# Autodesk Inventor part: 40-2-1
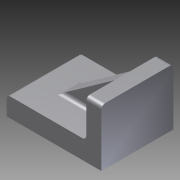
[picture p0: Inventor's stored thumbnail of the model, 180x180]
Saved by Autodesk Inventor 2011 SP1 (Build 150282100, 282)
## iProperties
Created: 2014-01
Part Number: 40-2-1
Document SubType Name: Modeling
Designer: Administrator
Density: 1 g/cm^3
Author: Administrator
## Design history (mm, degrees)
sketch "草图1"
  geometry: L1 (-12.5, 9.5)-(12.5, 9.5); L2 (12.5, 9.5)-(12.5, -9.5); L3 (12.5, -9.5)-(-12.5, -9.5); L4 (-12.5, -9.5)-(-12.5, 9.5); 3 further points
  constraints: 8 end point, 2 midpoint, 2 parallel, 1 horizontal, 1 horizontal alignment, 1 perpendicular, 1 vertical alignment
  dimensions: "d0" = 25 distance of L1.start L1.end; "d1" = 19 distance of L1.end L2.end
extrude "拉伸1" new body sketch "草图1" distance "d2" = 5; taper "d3" = 0 deg
sketch "草图2"
  geometry: L1 (12.5, -9.5)-(-12.5, -9.5) reference; L2 (12.5, 9.5)-(8.5, 9.5); L3 (8.5, 9.5)-(8.5, -9.5); L4 (8.5, -9.5)-(12.5, -9.5); L5 (12.5, -9.5)-(12.5, 9.5); 1 further point
  constraints: 8 end point, 2 parallel, 1 horizontal, 1 perpendicular, 1 point on line
  dimensions: "d4" = 4 distance between parallel lines of L5 L3
extrude "拉伸2" join sketch "草图2" distance "d5" = 10; taper "d6" = 0 deg
sketch "草图3"
  geometry: L1 (-8.5, 5)-(-8.5, 15) reference; L2 (-8.5, 15)-(-12.5, 15) reference; L3 (12.5, 5)-(-8.5, 5) reference; L4 (-8.5, 15)-(5.5, 5); 1 further point
  constraints: 2 end point, 1 point on line
  dimensions: "d7" = 7 distance of L4.end L3.start
feature "加强筋1" sketch "草图3" dims "d8" = 1, "d9" = 4, "d10" = 0
fillet "圆角1" dims "d11" = 1
fillet "圆角2" dims "d12" = 1
node "实体1"
